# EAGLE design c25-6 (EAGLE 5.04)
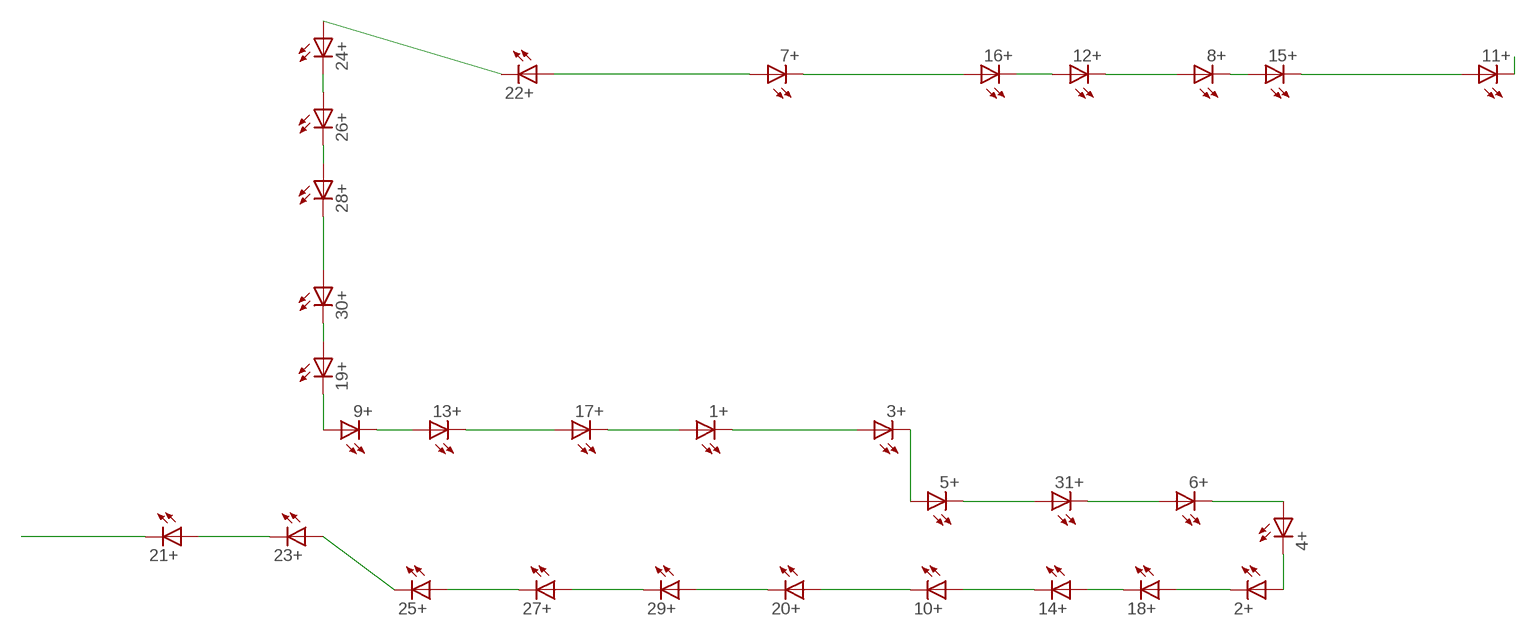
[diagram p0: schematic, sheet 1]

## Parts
1+  LED5MM  [LED5MM]
2+  LED5MM  [LED5MM]
3+  LED5MM  [LED5MM]
4+  LED5MM  [LED5MM]
5+  LED5MM  [LED5MM]
6+  LED5MM  [LED5MM]
7+  LED5MM  [LED5MM]
8+  LED5MM  [LED5MM]
9+  LED5MM  [LED5MM]
10+  LED5MM  [LED5MM]
11+  LED5MM  [LED5MM]
12+  LED5MM  [LED5MM]
13+  LED5MM  [LED5MM]
14+  LED5MM  [LED5MM]
15+  LED5MM  [LED5MM]
16+  LED5MM  [LED5MM]
17+  LED5MM  [LED5MM]
18+  LED5MM  [LED5MM]
19+  LED5MM  [LED5MM]
20+  LED5MM  [LED5MM]
21+  LED5MM  [LED5MM]
22+  LED5MM  [LED5MM]
23+  LED5MM  [LED5MM]
24+  LED5MM  [LED5MM]
25+  LED5MM  [LED5MM]
26+  LED5MM  [LED5MM]
27+  LED5MM  [LED5MM]
28+  LED5MM  [LED5MM]
29+  LED5MM  [LED5MM]
30+  LED5MM  [LED5MM]
31+  LED5MM  [LED5MM]

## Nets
MINUS: 21+.K(C)
MINUS6: 11+.K(C)
N$2: 21+.A 23+.K(C)
N$4: 23+.A 25+.K(C)
N$7: 25+.A 27+.K(C)
N$8: 27+.A 29+.K(C)
N$9: 20+.K(C) 29+.A
N$10: 10+.K(C) 20+.A
N$11: 10+.A 14+.K(C)
N$12: 14+.A 18+.K(C)
N$13: 2+.K(C) 18+.A
N$14: 2+.A 4+.K(C)
N$15: 4+.A 6+.K(C)
N$16: 6+.A 31+.K(C)
N$17: 5+.K(C) 31+.A
N$18: 3+.K(C) 5+.A
N$19: 1+.K(C) 3+.A
N$20: 1+.A 17+.K(C)
N$21: 13+.K(C) 17+.A
N$22: 9+.K(C) 13+.A
N$23: 9+.A 19+.K(C)
N$24: 19+.A 30+.K(C)
N$25: 28+.K(C) 30+.A
N$26: 24+.K(C) 26+.A
N$27: 22+.K(C) 24+.A
N$28: 26+.K(C) 28+.A
N$29: 11+.A 15+.K(C)
N$30: 8+.K(C) 15+.A
N$31: 8+.A 12+.K(C)
N$32: 12+.A 16+.K(C)
N$33: 7+.K(C) 16+.A
PLUS: 7+.A 22+.A

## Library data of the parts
1+ 2+ 3+ 4+ 5+ 6+ 7+ 8+ 9+ 10+ 11+ 12+ 13+ 14+ 15+ 16+ 17+ 18+ 19+ 20+ 21+ 22+ 23+ 24+ 25+ 26+ 27+ 28+ 29+ 30+ 31+ = led(2):LED: LED

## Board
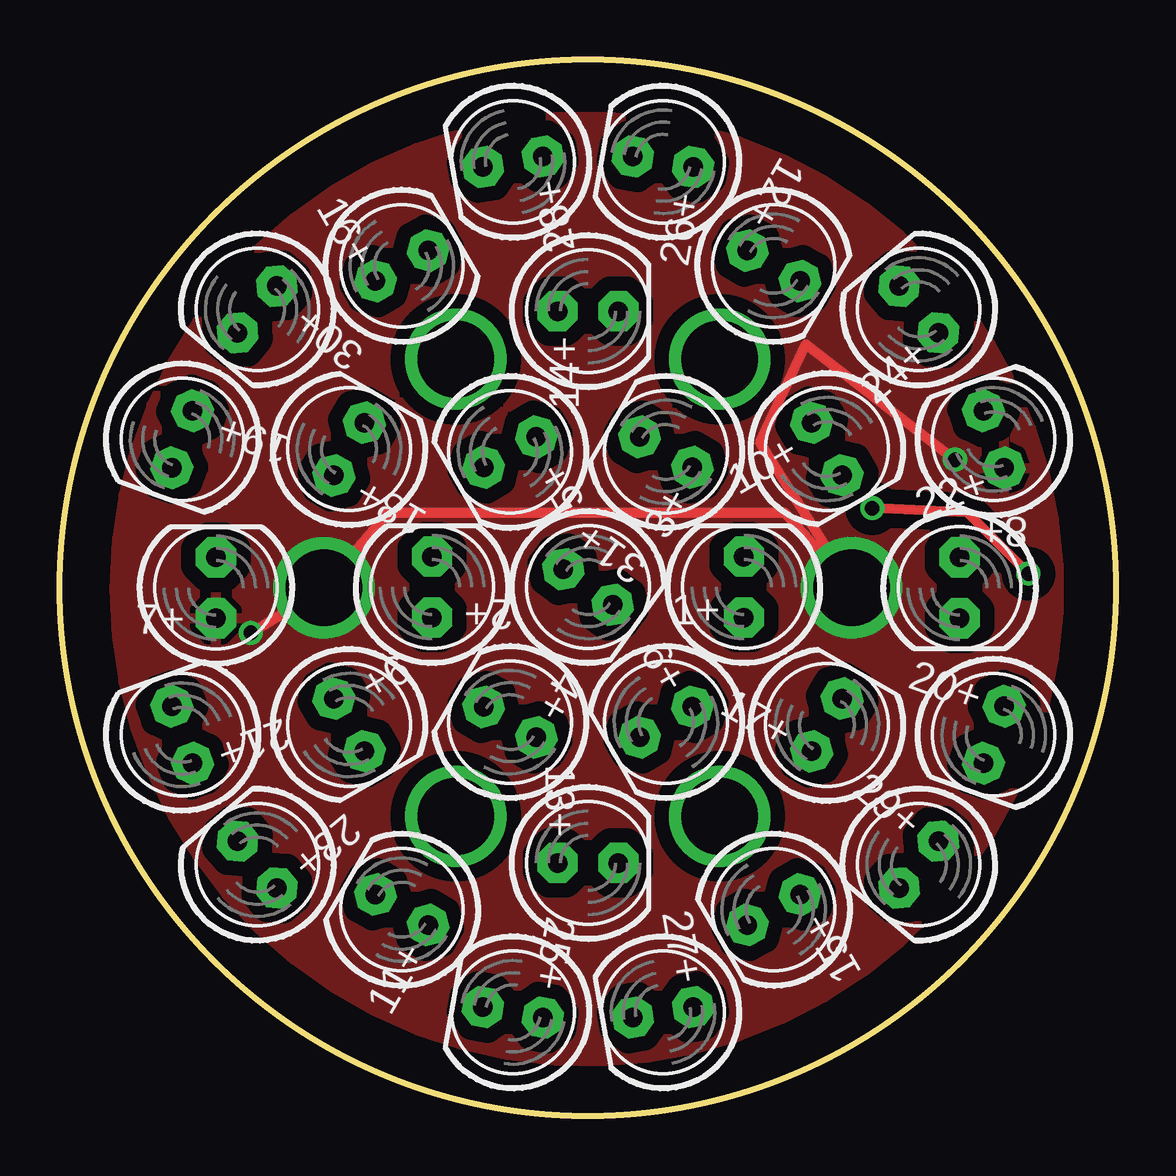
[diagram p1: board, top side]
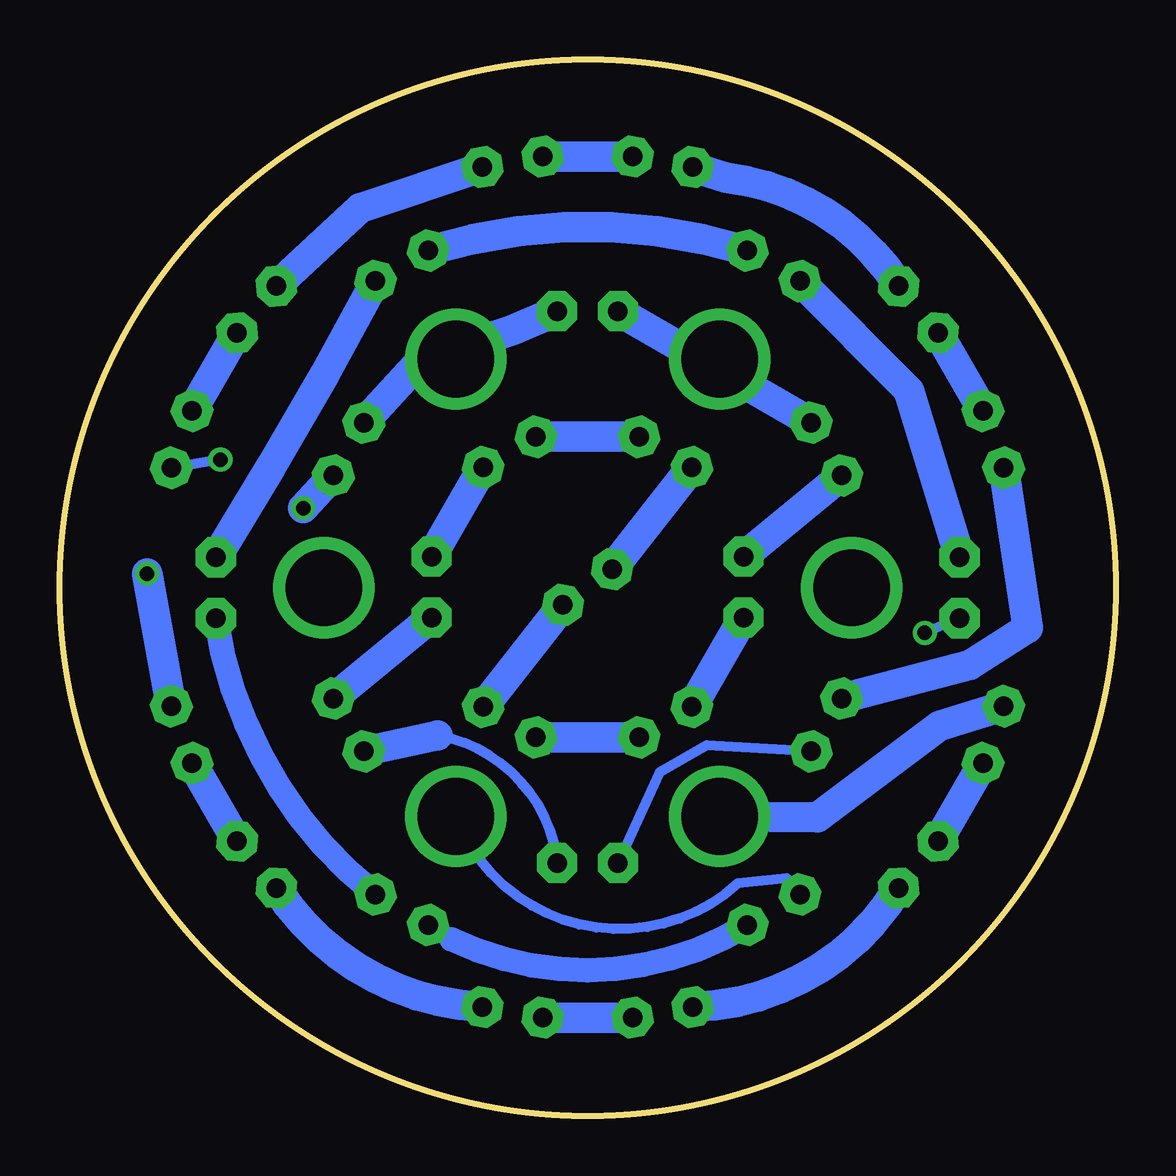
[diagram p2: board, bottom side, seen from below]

Size 44 x 44 mm. Coordinates in mm from the lower left corner, seen from the top.
Outline: circle at 22,22 radius 22
Copper layers (1*16): Top 0.035mm / dielectric 1.5mm / Bottom 0.035mm
Design rules "default": minimum track width 10mil, minimum drill 24mil, track to track 8mil, track to pad 8mil, pad to pad 8mil, via to via 8mil, smd to smd 8mil, copper to edge 40mil, drill to drill 8mil, minimum pad ring 10mil, minimum via ring 8mil, stop-mask expansion 4mil, vias tented up to drill 0mil, thermal gap 10mil

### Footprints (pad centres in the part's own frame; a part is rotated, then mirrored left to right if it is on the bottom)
LED5MM = drill 0.813 pad 1.676 octagon: A -1.27,0; K 1.27,0

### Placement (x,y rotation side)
1+  28.51,22.03 90 top
2+  15.51,22.03 90 top
3+  25.26,27.66 150 top
4+  18.76,16.4 150 top
5+  18.76,27.66 210 top
6+  25.26,16.4 210 top
7+  6.5,22 90 top
8+  37.5,22 270 top
9+  12.05,16.28 300 top
10+  31.97,27.78 300 top
11+  14.25,8.58 150 top
12+  29.75,35.42 330 top
13+  22.01,10.53 0 top
14+  22.01,33.53 0 top
15+  29.75,8.58 210 top
16+  14.25,35.42 30 top
17+  31.97,16.28 60 top
18+  12.05,27.78 60 top
19+  5.1,28.19 250 top
20+  38.92,15.87 250 top
21+  5.1,15.87 110 top
22+  38.92,28.19 110 top
23+  8.22,10.46 130 top
24+  35.8,33.6 130 top
25+  18.88,4.3 170 top
26+  25.14,39.76 170 top
27+  25.14,4.3 190 top
28+  18.88,39.76 190 top
29+  35.8,10.46 230 top
30+  8.22,33.6 230 top
31+  22.01,22.03 324.1 top

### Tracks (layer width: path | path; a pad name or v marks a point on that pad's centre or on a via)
MINUS  (via drill 3.2)
  Bottom 1.27: v16.5,12.47 12.43,12.43 7.35,16.24 21+.K
MINUS6  (via drill 3.2)
  Bottom 0.406: 11+.K 13.7,9.89 15.73,9.68 arc111 v27.5,12.47
N$2
  Bottom 1.27: 23+.K 21+.A
N$4
  Bottom 1.27: 23+.A arc57 25+.K
N$6  (via drill 3.2)
  other vias: 27.5,31.53
N$7
  Bottom 1.27: 25+.A 27+.K
N$8
  Bottom 1.27: 27+.A arc54 29+.K
N$9
  Bottom 1.27: 29+.A 20+.K
N$10  (via drill 0.6)
  Top 0.406: v40.37,22.59 37.83,25.13 v33.86,25.32
  Bottom 1.27: 20+.A v40.37,22.59 | v33.86,25.32 10+.K
N$11
  Bottom 1.27: 10+.A 28.94,31.48 25.13,32.75 14+.K
N$12
  Bottom 1.27: 18+.K 14+.A
N$13
  Bottom 1.27: 2+.K 18+.A
N$14
  Bottom 1.27: 4+.K 2+.A
N$15
  Bottom 1.27: 4+.A 6+.K
N$16
  Bottom 1.27: 31+.K 6+.A
N$17
  Bottom 1.27: 31+.A 5+.K
N$18
  Bottom 1.27: 5+.A 3+.K
N$19
  Bottom 1.27: 1+.K 3+.A
N$20
  Bottom 1.27: 1+.A 17+.K
N$21
  Bottom 0.406: 13+.K 23.4,11.36 arc-64 28.26,15.85
  Bottom 1.27: 28.26,15.85 17+.A
N$22
  Bottom 0.406: 9+.K 17.05,15.43 19.01,14.31 13+.A
N$23
  Bottom 1.27: 9+.A 6.08,18.78 3.65,20.33 19+.K
N$24
  Bottom 1.27: 19+.A 30+.K
N$25
  Bottom 1.27: 30+.A arc-51 16.24,39.1 28+.K
N$26
  Bottom 1.27: 26+.A 31.48,37.83 24+.K
N$27
  Bottom 1.27: 22+.K 24+.A
N$28
  Bottom 1.27: 28+.A 26+.K
N$29
  Bottom 0.406: 27.67,7.35 15+.K
  Bottom 1.016: 11+.A arc57 27.67,7.35
N$30
  Bottom 1.016: 15+.A arc43 8+.K
N$31
  Bottom 1.27: 8+.A arc-4 12+.K
N$32
  Bottom 1.27: 16+.K arc-34 12+.A
N$33
  Bottom 1.27: 7+.K 8.62,30.21 16+.A
PLUS  (via drill 0.6, 3.2)
  Top 0.406: v37.31,27.34 31.1,32.15 29.18,28.05 v33,22 30.21,25.13 13.7,25.13 v11,22 v7.95,20.12
  Bottom 0.406: v37.31,27.34 22+.A | 7+.A v7.95,20.12
  pour Top (isolate 0.61): 22.59,41.64 arc184 22.59,2.27 arc176
X  (via drill 3.2)
  other vias: 16.5,31.53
